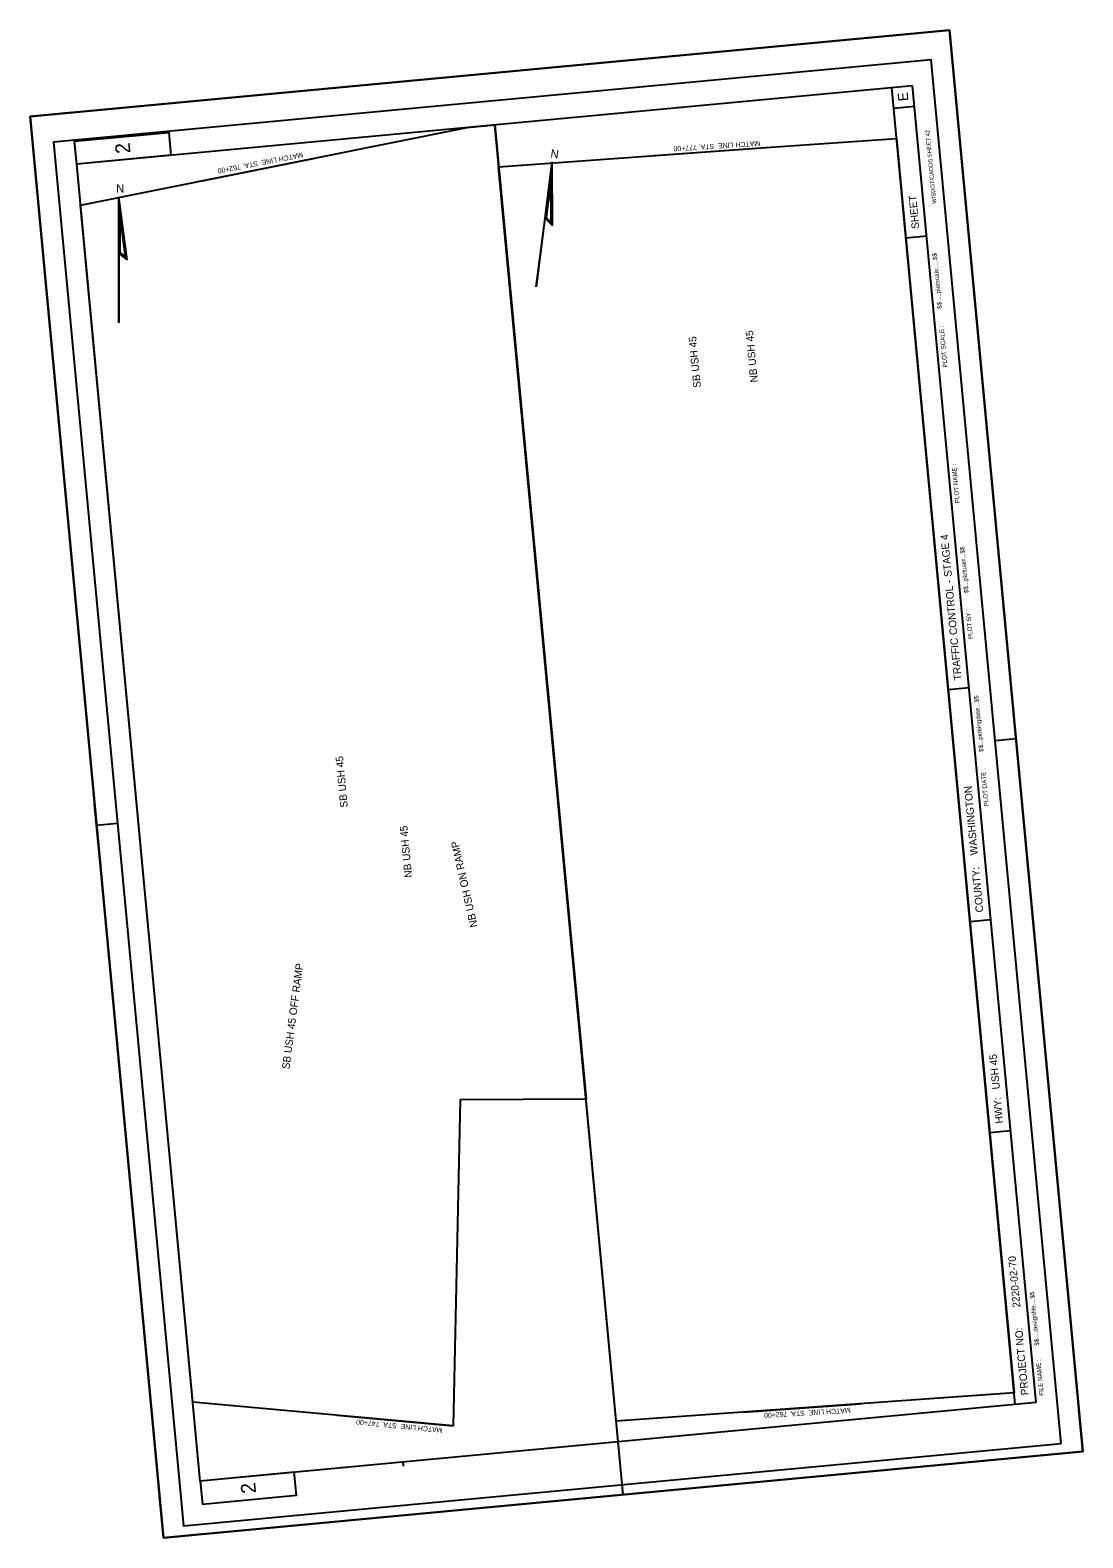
# Model space of a CAD drawing. Extents: x 355777 to 358875, y 194844 to 202274.
import ezdxf

# ---------------------------------------------------------------- set-up
doc = ezdxf.new("R2010")
doc.units = 0
for name, color, linetype in [('Default', 7, 'Continuous'), ('P_ALI_20', 7, 'Continuous'), ('P_ALI_200_Equation', 7, 'Continuous'), ('P_ALI_20_PIData', 7, 'Continuous'), ('P_ALI_50_Equation', 7, 'Continuous'), ('P_ALI_50_PIData', 7, 'Continuous'), ('P_ALI_50_Sta', 7, 'Continuous')]:
    doc.layers.add(name, color=color, linetype=linetype)

msp = doc.modelspace()

# ---------------------------------------------------------------- linework, layer by layer
for points in [[(357435.3, 196584.4), (357276.6, 198277), (356181.4, 198174.3), (356340.1, 196481.7)], [(357409.3, 196594), (357254.8, 198241.8), (356209.4, 198143.7), (356363.9, 196496)]]:
    msp.add_lwpolyline(points, close=True)
at = {"layer": 'Default'}
for points in [[(356241.5, 198068.7), (356702.1, 198161.1), (356734.8, 198164.1), (356843.5, 197004.1), (356693.8, 197003.4), (356685.4, 196615.1), (356375.2, 196643.3)], [(356241.5, 198068.7), (356702.1, 198161.1), (356734.8, 198164.1), (356843.5, 197004.1), (356693.8, 197003.4), (356685.4, 196615.1), (356375.2, 196643.3)], [(356241.5, 198068.7), (356702.1, 198161.1), (356734.8, 198164.1), (356843.5, 197004.1), (356693.8, 197003.4), (356685.4, 196615.1), (356375.2, 196643.3)], [(356739.4, 198114.4), (357063.7, 198137.5), (357213.3, 198148.1), (357353.4, 196654.3), (357353.4, 196654.3), (356879.5, 196620.6)], [(356739.4, 198114.4), (357063.7, 198137.5), (357213.3, 198148.1), (357353.4, 196654.3), (357353.4, 196654.3), (356879.5, 196620.6)], [(356739.4, 198114.4), (357063.7, 198137.5), (357213.3, 198148.1), (357353.4, 196654.3), (357353.4, 196654.3), (356879.5, 196620.6)]]:
    msp.add_lwpolyline(points, close=True, dxfattribs=at)
at = {"layer": 'P_ALI_20'}
msp.add_line((356881.8, 196596), (356734.8, 198164.1), dxfattribs=at)
at = {"layer": 'P_ALI_200_Equation'}
for p, q in [((357276.6, 198277), (357226.8, 198272.3)), ((357281.3, 198227.2), (357276.6, 198277)), ((357232.6, 198210.8), (356236.9, 198117.4)), ((357354.7, 196640.4), (357207.7, 198208.5)), ((357379.6, 196642.7), (357232.6, 198210.8)), ((357234.9, 198185.9), (357210, 198183.6)), ((356231.2, 198178.9), (356181.4, 198174.3)), ((356186.1, 198124.5), (356181.4, 198174.3)), ((356843.5, 197004.1), (356734.8, 198164.1)), ((356384, 196549.3), (356236.9, 198117.4)), ((357249.4, 198031.6), (357224.5, 198029.3)), ((357299.8, 197494), (357274.9, 197491.6)), ((357358.1, 197408.3), (357353.4, 197458.1)), ((357355.7, 197433.2), (357330.8, 197430.8)), ((356262.9, 197305.6), (356258.2, 197355.3)), ((356260.5, 197330.5), (356285.4, 197332.8)), ((357325.7, 197217.7), (357300.8, 197215.3)), ((357349.3, 196966.3), (357324.4, 196963.9)), ((357379.6, 196642.7), (356384, 196549.3)), ((356878.3, 196633.4), (356878.3, 196633.4)), ((357435.3, 196584.4), (357430.7, 196634.2)), ((356887.7, 196533), (356881.8, 196596)), ((357435.3, 196584.4), (357385.5, 196579.7)), ((356625.4, 196572), (356625.9, 196567)), ((356340.1, 196481.7), (356335.5, 196531.5)), ((356912.6, 196535.4), (356862.8, 196530.7)), ((356389.9, 196486.4), (356340.1, 196481.7))]:
    msp.add_line(p, q, dxfattribs=at)
for points in [[(356236.9, 198117.4), (356234.4, 198144.8), (356346.4, 198155.3), (356348.9, 198128)], [(356384, 196549.3), (356386.6, 196521.9), (356498.6, 196532.5), (356496, 196559.8)]]:
    msp.add_lwpolyline(points, close=True, dxfattribs=at)
at = {"layer": 'P_ALI_20_PIData'}
for p, q in [((356794.7, 198053.1), (356803.2, 198120)), ((356803.6, 198044.4), (356803.2, 198120)), ((356795.5, 198053.4), (356802.5, 198108.7)), ((356796.3, 198053.6), (356801.8, 198097.4)), ((356802.1, 198047.9), (356801.8, 198097.4)), ((356802.9, 198046.2), (356802.5, 198108.7)), ((356297, 198003.6), (356287, 198078.6)), ((356287, 198011.1), (356287, 198078.6)), ((356287.8, 198011.5), (356287.8, 198067.3)), ((356296, 198005.3), (356287.8, 198067.3)), ((356288.5, 198011.8), (356288.5, 198056)), ((356295, 198006.9), (356288.5, 198056)), ((356784.2, 197971.3), (356794.7, 198053.1)), ((356784.5, 197971.2), (356794.9, 198052.9)), ((356794.7, 198053.1), (356803.6, 198044.4)), ((356795.5, 198053.4), (356802.9, 198046.2)), ((356796.3, 198053.6), (356802.1, 198047.9)), ((356287, 198011.1), (356297, 198003.6)), ((356287, 197928.6), (356287, 198011.1)), ((356287.3, 197928.6), (356287.3, 198010.9)), ((356287.8, 198011.5), (356296, 198005.3)), ((356288.5, 198011.8), (356295, 198006.9))]:
    msp.add_line(p, q, dxfattribs=at)
for points in [[(356803.2, 198120), (356803.2, 198120)], [(356287, 198078.5), (356287, 198078.5)]]:
    msp.add_lwpolyline(points, dxfattribs=at)
at = {"layer": 'P_ALI_50_Equation'}
msp.add_lwpolyline([(356340.1, 196481.7), (356181.4, 198174.3), (357276.6, 198277), (357435.3, 196584.4)], close=True, dxfattribs=at)
at = {"layer": 'P_ALI_50_PIData'}
for p, q in [((356924.7, 198127.6), (357063.7, 198137.5)), ((356384.2, 198097.3), (356520.8, 198124.7)), ((357031.5, 196631.4), (357170.4, 196641.3)), ((356546.7, 196627.7), (356685.4, 196615.1))]:
    msp.add_line(p, q, dxfattribs=at)

# ---------------------------------------------------------------- texts
at = {"layer": 'P_ALI_200_Equation'}
for s, height, rotation, p in [('E', 12, 95.3579, (357227.6, 198192.9)), ('WISDOT/CADDS SHEET 42', 5, 95.3579, (357260.8, 198070.5)), ('2', 17.5, 95.3579, (356301, 198130.7)), ('SHEET ', 9, 95.3579, (357240.5, 198040.8)), ('$$.....plotscale.....$$', 5.4, 95.3579, (357267.5, 197945.4)), ('PLOT SCALE : ', 5.4, 95.3579, (357274.1, 197875.5)), ('PLOT NAME :                      ', 5.4, 95.3579, (357288.7, 197713.9)), ('TRAFFIC CONTROL - STAGE 4', 9, 95.3579, (357290.9, 197503.2)), ('$$...plotuser...$$', 5.4, 95.3578, (357299.3, 197606.9)), ('PLOT BY :', 5.4, 95.3578, (357304.4, 197552.2)), ('$$...plottingdate...$$', 5.4, 95.3578, (357317, 197417.7)), ('PLOT DATE :', 5.4, 95.3578, (357323.1, 197353)), (' WASHINGTON', 9, 95.3579, (357310.7, 197291.6)), ('COUNTY:', 9, 95.3579, (357316.8, 197226.9)), (' USH 45', 9, 95.3579, (357336.9, 197012.8)), ('HWY:', 9, 95.3579, (357340.4, 196975.5)), (' 2220-02-70', 9, 95.3579, (357361.3, 196753)), ('$$....designfile....$$', 5.4, 95.3578, (357383.3, 196710.8)), ('PROJECT NO:', 9, 95.3579, (357370.7, 196651.9)), ('FILE NAME :', 5.4, 95.3579, (357388.9, 196651.1)), ('2', 17.5, 95.3579, (356450.6, 196535.2))]:
    msp.add_text(s, height=height, rotation=rotation, dxfattribs=at).set_placement(p)
at = {"layer": 'P_ALI_20_PIData'}
msp.add_text('N', height=10, rotation=352.7231, dxfattribs=at).set_placement((356800.8, 198125.3))
msp.add_text('N', height=10, dxfattribs=at).set_placement((356283.9, 198083.5))
at = {"layer": 'P_ALI_50_Sta'}
for s, height, rotation, p in [('MATCH LINE  STA. 762+00', 6, 190.9331, (356505.8, 198131.6)), ('MATCH LINE  STA. 777+00', 6, 183.6562, (357050.7, 198145.2)), ('NB USH 45', 9, 95.3579, (357048.2, 197857.9)), ('SB USH 45', 9, 95.3579, (356980.4, 197851.5)), ('SB USH 45', 9, 95.3579, (356559.8, 197351.7)), ('NB USH 45', 9, 95.3579, (356636.4, 197268.3)), ('NB USH ON RAMP', 9, 102.7467, (356714.5, 197209.7)), ('SB USH 45 OFF RAMP', 9, 82.3996, (356490.1, 197039.2)), ('MATCH LINE  STA. 747+00', 6, 174.3993, (356672.9, 196612.6)), ('MATCH LINE  STA. 762+00', 6, 183.6562, (357158.6, 196636.7))]:
    msp.add_text(s, height=height, rotation=rotation, dxfattribs=at).set_placement(p)

doc.saveas('drawing.dxf')
